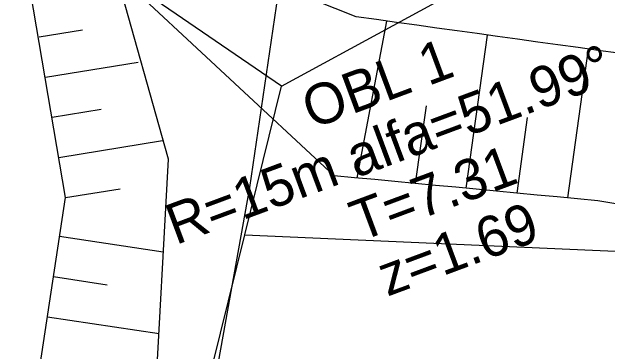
# Model space of a CAD drawing. Extents: x -583721 to -583071, y -1166145 to -1165065.
# Drawn here: x -583385.69 to -583356.45, y -1165662.29 to -1165645.62 of the extents above; entities that cross this region are included whole.
import ezdxf

# ---------------------------------------------------------------- set-up
doc = ezdxf.new("R2010")
doc.units = 0
for name, color, linetype in [('01_DOPRAVA', 7, 'Continuous'), ('03_PC_POPIS_NAVRH', 7, 'Continuous'), ('14', 7, 'Continuous'), ('21', 7, 'Continuous'), ('_Rozpiska', 7, 'Continuous'), ('Rámy', 7, 'Continuous'), ('TISK', 7, 'Continuous')]:
    doc.layers.add(name, color=color, linetype=linetype)

msp = doc.modelspace()

# ---------------------------------------------------------------- linework, layer by layer
at = {"layer": '01_DOPRAVA'}
msp.add_line((-583374.25, -1165656.58), (-583372.44, -1165649.28), dxfattribs=at)
for points in [[(-583372.44, -1165649.28), (-583380.56, -1165643.71), (-583384.65, -1165640.82), (-583384.34, -1165635.13), (-583380.11, -1165632.63), (-583380.02, -1165632.08), (-583374.92, -1165587.93), (-583361.04, -1165570.69)], [(-583372.44, -1165649.28), (-583361.47, -1165643.29), (-583352.56, -1165623.43)], [(-583374.25, -1165656.58), (-583351.23, -1165657.59), (-583331.17, -1165652.35), (-583245.16, -1165665.31), (-583236.84, -1165691.62), (-583230.99, -1165795.18)], [(-583387, -1165801.65), (-583385.87, -1165777.24), (-583381.45, -1165708.45), (-583381.45, -1165685.69), (-583374.25, -1165656.58)]]:
    msp.add_lwpolyline(points, dxfattribs=at)
at = {"layer": '03_PC_POPIS_NAVRH'}
msp.add_lwpolyline([(-583379.741, -1165694.56), (-583379.57, -1165690.87), (-583377.81, -1165675.52), (-583374, -1165654.25), (-583372.12, -1165641.43), (-583371.79, -1165638.08), (-583372.3, -1165610.54), (-583370.49, -1165593.91), (-583364.41, -1165578.01), (-583353.13, -1165562.49), (-583348.06, -1165556.64), (-583342.86, -1165548.6), (-583339.71, -1165538.95), (-583338.99, -1165532.81), (-583338.38, -1165526.75), (-583340.63, -1165516.91), (-583347.05, -1165504.24), (-583351.75, -1165493.85), (-583352.9, -1165478.37), (-583347.252, -1165452.669)], dxfattribs=at)
at = {"layer": '14'}
for p, q in [((-583367.29, -1165646.072), (-583368.742, -1165653.781)), ((-583362.337, -1165646.759), (-583363.382, -1165654.29)), ((-583357.385, -1165647.446), (-583358.399, -1165654.762)), ((-583365.343, -1165650.235), (-583365.873, -1165654.054)), ((-583360.376, -1165650.814), (-583360.891, -1165654.526))]:
    msp.add_line(p, q, dxfattribs=at)
at = {"layer": '21'}
for points in [[(-583355.898, -1165647.652), (-583356.889, -1165647.515), (-583357.879, -1165647.377), (-583358.87, -1165647.24), (-583359.86, -1165647.103), (-583360.851, -1165646.965), (-583361.842, -1165646.828), (-583362.832, -1165646.691), (-583363.823, -1165646.553), (-583364.813, -1165646.416), (-583365.804, -1165646.278), (-583366.794, -1165646.141), (-583367.785, -1165646.004), (-583368.775, -1165645.866), (-583377.739, -1165642.29)], [(-583355.918, -1165655.071), (-583356.904, -1165654.904), (-583357.901, -1165654.81), (-583358.897, -1165654.715), (-583359.893, -1165654.621), (-583360.89, -1165654.526), (-583361.886, -1165654.432), (-583362.883, -1165654.337), (-583363.879, -1165654.243), (-583364.876, -1165654.148), (-583365.872, -1165654.054), (-583366.869, -1165653.959), (-583367.865, -1165653.865), (-583368.862, -1165653.77), (-583369.858, -1165653.676), (-583380.56, -1165643.71)]]:
    msp.add_lwpolyline(points, dxfattribs=at)
at = {"layer": '_Rozpiska'}
for points in [[(-583384.35, -1165646.85), (-583382.22, -1165646.51)], [(-583384.03, -1165648.83), (-583379.49, -1165648.09)], [(-583383.7, -1165650.8), (-583381.3, -1165650.41)], [(-583383.38, -1165652.78), (-583378.29, -1165651.94)], [(-583383.06, -1165654.75), (-583380.37, -1165654.31)], [(-583383.35, -1165656.65), (-583378.25, -1165657.42)], [(-583383.65, -1165658.63), (-583381, -1165659.03)], [(-583383.94, -1165660.61), (-583378.46, -1165661.43)]]:
    msp.add_lwpolyline(points, dxfattribs=at)
at = {"layer": 'Rámy'}
for points in [[(-583383.586, -1165694.294), (-583383.47, -1165691.82), (-583384.84, -1165666.54), (-583383.06, -1165654.75), (-583385.19, -1165642.1)], [(-583381.667, -1165694.427), (-583381.45, -1165685.69), (-583378.66, -1165665.11), (-583378, -1165652.86), (-583380.56, -1165643.71)]]:
    msp.add_lwpolyline(points, dxfattribs=at)

# ---------------------------------------------------------------- texts
at = {"layer": 'TISK'}
for s, p in [('OBL 1', (-583370.947, -1165651.395)), ('R=15m alfa=51.99%%d', (-583377.638, -1165657.088)), ('  T=7.31', (-583369.982, -1165657.438)), ('   z=1.69', (-583369.336, -1165660.399))]:
    msp.add_text(s, height=2, rotation=20.4208, dxfattribs=at).set_placement(p)

doc.saveas('drawing.dxf')
